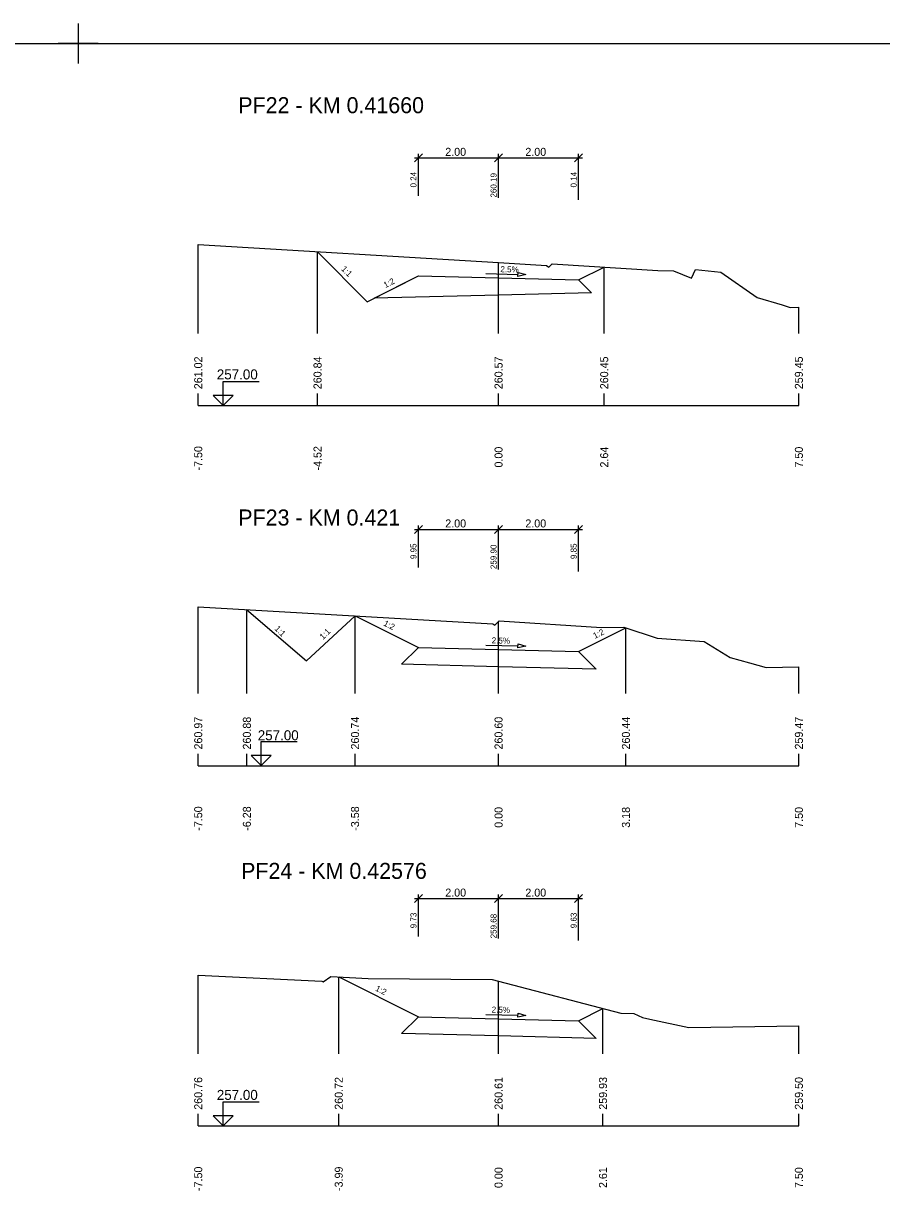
# Model space of a CAD drawing. Extents: x -5 to 1895, y -2 to 602.
# Drawn here: x 1456.4 to 1670.6, y 307.9 to 602.4 of the extents above; entities that cross this region are included whole.
import ezdxf

# ---------------------------------------------------------------- set-up
doc = ezdxf.new("R2010")
doc.units = 0
for name, color, linetype in [('KOTA', 7, 'Continuous'), ('KOTA_DELKY', 7, 'Continuous'), ('KOTA_DELKY_CONT', 7, 'Continuous'), ('NS_TELESO_VOZOVKY', 7, 'Continuous'), ('NS_V_PF', 7, 'Continuous'), ('REZY_PF_PUVODNI', 7, 'Continuous'), ('SESTAVY_REZU_PF', 7, 'Continuous'), ('SKLON', 7, 'Continuous'), ('SVK', 7, 'Continuous')]:
    doc.layers.add(name, color=color, linetype=linetype)

msp = doc.modelspace()

# ---------------------------------------------------------------- linework, layer by layer
for p, q in [((1470, 602.39), (1470, 592.39)), ((1470, 602.39), (1470, 592.39)), ((1470, 602.39), (1470, 592.39)), ((1470, 602.39), (1470, 592.39)), ((1470, 602.39), (1470, 592.39)), ((1470, 602.39), (1470, 592.39)), ((1470, 602.39), (1470, 592.39)), ((1470, 602.39), (1470, 592.39)), ((1470, 602.39), (1470, 592.39)), ((1470, 602.39), (1470, 592.39)), ((1470, 602.39), (1470, 592.39)), ((1470, 602.39), (1470, 592.39)), ((1470, 602.39), (1470, 592.39)), ((1470, 602.39), (1470, 592.39)), ((1470, 602.39), (1470, 592.39)), ((1470, 602.39), (1470, 592.39)), ((1470, 602.39), (1470, 592.39)), ((1470, 602.39), (1470, 592.39)), ((1470, 602.39), (1470, 592.39)), ((1470, 602.39), (1470, 592.39)), ((1475, 597.39), (1465, 597.39)), ((1475, 597.39), (1465, 597.39)), ((1475, 597.39), (1465, 597.39)), ((1475, 597.39), (1465, 597.39)), ((1475, 597.39), (1465, 597.39)), ((1475, 597.39), (1465, 597.39)), ((1475, 597.39), (1465, 597.39)), ((1475, 597.39), (1465, 597.39)), ((1475, 597.39), (1465, 597.39)), ((1475, 597.39), (1465, 597.39)), ((1475, 597.39), (1465, 597.39)), ((1475, 597.39), (1465, 597.39)), ((1475, 597.39), (1465, 597.39)), ((1475, 597.39), (1465, 597.39)), ((1475, 597.39), (1465, 597.39)), ((1475, 597.39), (1465, 597.39)), ((1475, 597.39), (1465, 597.39)), ((1475, 597.39), (1465, 597.39)), ((1475, 597.39), (1465, 597.39)), ((1475, 597.39), (1465, 597.39))]:
    msp.add_line(p, q)
msp.add_lwpolyline([(0, 597.39), (1890, 597.39), (1890, 3.39), (0, 3.39)], close=True)
at = {"layer": 'KOTA'}
for points in [[(1506.22, 509.5), (1503.72, 509.5), (1506.22, 507), (1506.22, 513), (1515.22, 513)], [(1506.22, 507), (1508.72, 509.5), (1506.22, 509.5)], [(1515.74, 419.55), (1513.24, 419.55), (1515.74, 417.05), (1515.74, 423.05), (1524.74, 423.05)], [(1515.74, 417.05), (1518.24, 419.55), (1515.74, 419.55)], [(1506.22, 329.5), (1503.72, 329.5), (1506.22, 327), (1506.22, 333), (1515.22, 333)], [(1506.22, 327), (1508.72, 329.5), (1506.22, 329.5)]]:
    msp.add_lwpolyline(points, dxfattribs=at)
at = {"layer": 'KOTA_DELKY'}
for points in [[(1554, 567.85), (1556, 569.85)], [(1554, 568.85), (1576, 568.85)], [(1555, 559.35), (1555, 569.85)], [(1574, 567.85), (1576, 569.85)], [(1574, 567.85), (1576, 569.85)], [(1574, 568.85), (1596, 568.85)], [(1575, 558.85), (1575, 569.85)], [(1575, 558.85), (1575, 569.85)], [(1594, 567.85), (1596, 569.85)], [(1595, 558.35), (1595, 569.85)], [(1554, 475.02), (1556, 477.02)], [(1554, 476.02), (1576, 476.02)], [(1555, 466.52), (1555, 477.02)], [(1574, 475.02), (1576, 477.02)], [(1574, 475.02), (1576, 477.02)], [(1574, 476.02), (1596, 476.02)], [(1575, 466.02), (1575, 477.02)], [(1575, 466.02), (1575, 477.02)], [(1594, 475.02), (1596, 477.02)], [(1595, 465.52), (1595, 477.02)], [(1554, 382.79), (1556, 384.79)], [(1554, 383.79), (1576, 383.79)], [(1555, 374.29), (1555, 384.79)], [(1574, 382.79), (1576, 384.79)], [(1574, 382.79), (1576, 384.79)], [(1574, 383.79), (1596, 383.79)], [(1575, 373.79), (1575, 384.79)], [(1575, 373.79), (1575, 384.79)], [(1594, 382.79), (1596, 384.79)], [(1595, 373.29), (1595, 384.79)]]:
    msp.add_lwpolyline(points, dxfattribs=at)
at = {"layer": 'NS_TELESO_VOZOVKY'}
for points in [[(1575, 538.85), (1595, 538.35), (1595, 538.35), (1598.22, 535.13), (1575, 534.55), (1543.97, 533.78), (1555, 539.35), (1555, 539.35), (1575, 538.85)], [(1575, 446.02), (1595, 445.52), (1595, 445.52), (1599.41, 441.11), (1575, 441.72), (1550.8, 442.32), (1555, 446.52), (1555, 446.52), (1575, 446.02)], [(1575, 353.79), (1595, 353.29), (1595, 353.29), (1599.41, 348.88), (1575, 349.49), (1550.8, 350.09), (1555, 354.29), (1555, 354.29), (1575, 353.79)]]:
    msp.add_lwpolyline(points, dxfattribs=at)
at = {"layer": 'NS_V_PF'}
for points in [[(1529.79, 545.41), (1542.19, 532.88), (1555, 539.35), (1555, 539.35), (1575, 538.85), (1595, 538.35), (1595, 538.35), (1601.38, 541.54)], [(1512.04, 455.99), (1527.04, 443.23), (1539.16, 454.44)], [(1539.16, 454.44), (1555, 446.52), (1555, 446.52), (1575, 446.02), (1595, 445.52), (1595, 445.52), (1606.81, 451.42)], [(1535.09, 364.24), (1555, 354.29), (1555, 354.29), (1575, 353.79), (1595, 353.29), (1595, 353.29), (1601.08, 356.33)]]:
    msp.add_lwpolyline(points, dxfattribs=at)
at = {"layer": 'REZY_PF_PUVODNI'}
for points in [[(1500, 547.19), (1575, 542.7), (1587.01, 541.98), (1587.54, 541.54), (1588.36, 542.37), (1614.74, 540.69), (1618.72, 540.63), (1623.15, 538.79), (1624.15, 540.92), (1630.5, 540.26), (1639.56, 533.96), (1645.84, 532.09), (1647.82, 531.45), (1650, 531.51)], [(1500, 456.68), (1573.59, 452.46), (1574.03, 452.13), (1575, 453), (1575.18, 453.16), (1600.74, 451.54), (1606.32, 451.59), (1614.63, 448.83), (1626.38, 448.03), (1632.81, 444.01), (1637.66, 442.71), (1641.81, 441.49), (1650, 441.68)], [(1500, 364.64), (1530.87, 363.19), (1531.17, 363.02), (1533.15, 364.35), (1542.44, 363.84), (1573.38, 363.56), (1575, 363.14), (1605.53, 355.17), (1608.82, 355.09), (1610.97, 354.07), (1612.8, 353.7), (1622.53, 351.55), (1650, 352.01)]]:
    msp.add_lwpolyline(points, dxfattribs=at)
at = {"layer": 'SESTAVY_REZU_PF'}
for points in [[(1500, 507), (1650, 507)], [(1500, 417), (1650, 417)], [(1500, 327), (1650, 327)]]:
    msp.add_lwpolyline(points, dxfattribs=at)
at = {"layer": 'SKLON'}
for points in [[(1571.85, 539.93), (1579.85, 539.73)], [(1579.86, 540.23), (1581.85, 539.68), (1579.83, 539.23), (1579.86, 540.23)], [(1571.85, 447.1), (1579.85, 446.9)], [(1579.86, 447.4), (1581.85, 446.85), (1579.83, 446.4), (1579.86, 447.4)], [(1571.85, 354.87), (1579.85, 354.67)], [(1579.86, 355.17), (1581.85, 354.62), (1579.83, 354.17), (1579.86, 355.17)]]:
    msp.add_lwpolyline(points, dxfattribs=at)
at = {"layer": 'SVK'}
for points in [[(1500, 525), (1500, 547.19)], [(1529.79, 525), (1529.79, 545.41)], [(1575, 525), (1575, 542.7)], [(1601.38, 525), (1601.38, 541.54)], [(1650, 525), (1650, 531.51)], [(1500, 507), (1500, 510)], [(1529.79, 507), (1529.79, 510)], [(1575, 507), (1575, 510)], [(1601.38, 507), (1601.38, 510)], [(1650, 507), (1650, 510)], [(1500, 435), (1500, 456.68)], [(1512.14, 435), (1512.14, 455.69)], [(1539.16, 435), (1539.16, 454.44)], [(1575, 435), (1575, 453)], [(1606.81, 435), (1606.81, 451.42)], [(1650, 435), (1650, 441.68)], [(1500, 417), (1500, 420)], [(1512.14, 417), (1512.14, 420)], [(1539.16, 417), (1539.16, 420)], [(1575, 417), (1575, 420)], [(1606.81, 417), (1606.81, 420)], [(1650, 417), (1650, 420)], [(1500, 345), (1500, 364.64)], [(1535.09, 345), (1535.09, 364.24)], [(1575, 345), (1575, 363.14)], [(1601.08, 345), (1601.08, 356.33)], [(1650, 345), (1650, 352.01)], [(1500, 327), (1500, 330)], [(1535.09, 327), (1535.09, 330)], [(1575, 327), (1575, 330)], [(1601.08, 327), (1601.08, 330)], [(1650, 327), (1650, 330)]]:
    msp.add_lwpolyline(points, dxfattribs=at)

# ---------------------------------------------------------------- texts
at = {"layer": 'KOTA'}
for p in [(1504.64, 513.5), (1514.86, 423.35), (1504.64, 333.5)]:
    msp.add_text('257.00', height=2.5, dxfattribs=at).set_placement(p)
at = {"layer": 'KOTA_DELKY'}
for p in [(1561.69, 569.35), (1581.69, 569.35), (1561.69, 476.52), (1581.69, 476.52), (1561.69, 384.29), (1581.69, 384.29)]:
    msp.add_text('2.00', height=2, dxfattribs=at).set_placement(p)
at = {"layer": 'KOTA_DELKY_CONT'}
for s, p in [('0.24', (1554.5, 561.44)), ('260.19', (1574.5, 558.93)), ('0.14', (1594.5, 561.44)), ('9.95', (1554.5, 468.61)), ('259.90', (1574.5, 466.1)), ('9.85', (1594.5, 468.61)), ('9.73', (1554.5, 376.38)), ('259.68', (1574.5, 373.86)), ('9.63', (1594.5, 376.38))]:
    msp.add_text(s, height=1.5, rotation=90, dxfattribs=at).set_placement(p)
at = {"layer": 'SESTAVY_REZU_PF'}
for s, p in [('PF22 - KM 0.41660', (1510, 580)), ('PF23 - KM 0.421', (1510, 477)), ('PF24 - KM 0.42576', (1510.7, 388.72))]:
    msp.add_text(s, height=4, dxfattribs=at).set_placement(p)
at = {"layer": 'SKLON'}
for s, rotation, p in [('1:1', 314.7121, (1535.59, 540.97)), ('2.5%', 358.5679, (1575.45, 540.3)), ('1:2', 26.8233, (1546.74, 536.3)), ('1:1', 314.7121, (1518.96, 451.1)), ('1:1', 44.7121, (1531.17, 448.41)), ('1:2', 333.4349, (1546.12, 452.08)), ('1:2', 26.5651, (1599.05, 448.66)), ('2.5%', 358.5679, (1573.27, 447.56)), ('1:2', 333.4349, (1544.08, 360.86)), ('2.5%', 358.5679, (1573.27, 355.33))]:
    msp.add_text(s, height=1.5, rotation=rotation, dxfattribs=at).set_placement(p)
at = {"layer": 'SVK'}
for s, p in [(' 261.02', (1501, 510.3)), (' 260.84', (1530.79, 510.3)), (' 260.57', (1576, 510.3)), (' 260.45', (1602.38, 510.3)), (' 259.45', (1651, 510.3)), (' -7.50', (1501, 490)), (' -4.52', (1530.79, 490)), ('  0.00', (1576, 490)), ('  2.64', (1602.38, 490)), ('  7.50', (1651, 490)), (' 260.97', (1501, 420.3)), (' 260.88', (1513.14, 420.3)), (' 260.74', (1540.16, 420.3)), (' 260.60', (1576, 420.3)), (' 260.44', (1607.81, 420.3)), (' 259.47', (1651, 420.3)), (' -7.50', (1501, 400)), (' -6.28', (1513.14, 400)), (' -3.58', (1540.16, 400)), ('  0.00', (1576, 400)), ('  3.18', (1607.81, 400)), ('  7.50', (1651, 400)), (' 260.76', (1501, 330.3)), (' 260.72', (1536.09, 330.3)), (' 260.61', (1576, 330.3)), (' 259.93', (1602.08, 330.3)), (' 259.50', (1651, 330.3)), (' -7.50', (1501, 310)), (' -3.99', (1536.09, 310)), ('  0.00', (1576, 310)), ('  2.61', (1602.08, 310)), ('  7.50', (1651, 310))]:
    msp.add_text(s, height=2, rotation=90, dxfattribs=at).set_placement(p)

doc.saveas('drawing.dxf')
